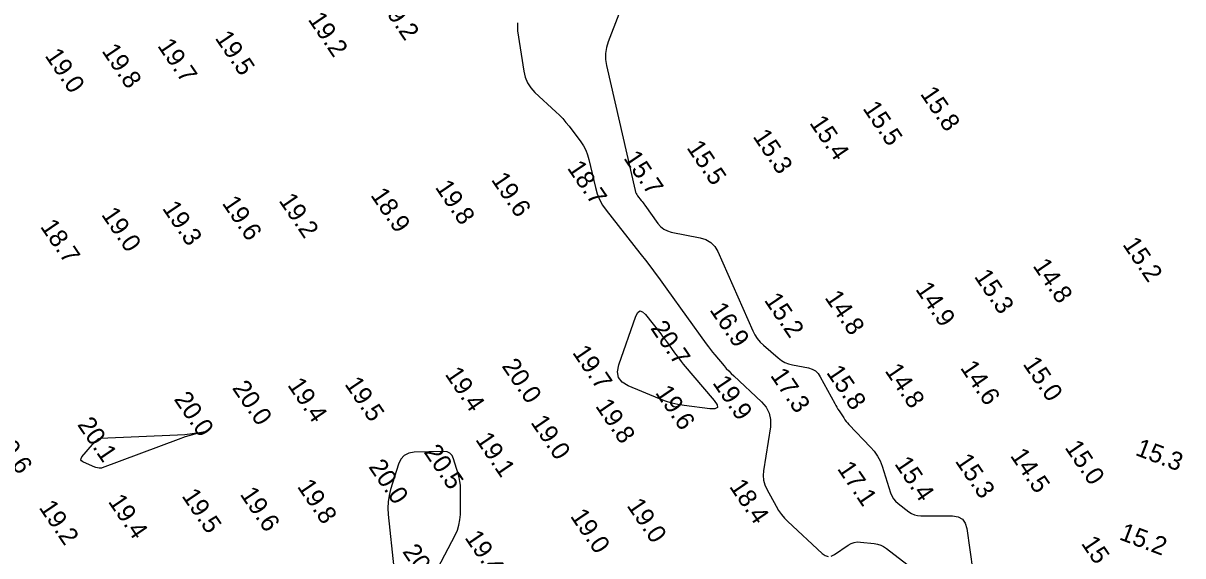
# Model space of a CAD drawing. Extents: x 824616 to 827440, y 158441 to 163197.
# Drawn here: x 826605.2 to 826924.3, y 160082.7 to 160229.3 of the extents above; entities that cross this region are included whole.
import ezdxf

# ---------------------------------------------------------------- set-up
doc = ezdxf.new("R2010")
doc.units = 0
for name, color, linetype in [('V-CHAN-CONT-EL16', 7, 'Continuous'), ('V-CHAN-CONT-EL18', 7, 'Continuous'), ('V-CHAN-CONT-EL20', 7, 'Continuous'), ('V-TOPO-SOUN', 7, 'Continuous')]:
    doc.layers.add(name, color=color, linetype=linetype)

msp = doc.modelspace()

# ---------------------------------------------------------------- linework, layer by layer
at = {"layer": 'V-CHAN-CONT-EL16'}
msp.add_lwpolyline([(826769.1, 160231.82), (826766.18, 160224.2), (826765.7, 160222.6), (826765.46, 160220.98), (826765.47, 160219.34), (826765.72, 160217.69), (826773.6, 160183.22), (826773.71, 160182.84), (826773.86, 160182.48), (826774.05, 160182.13), (826774.28, 160181.8), (826775.28, 160180.53), (826775.52, 160180.22), (826775.77, 160179.9), (826776.01, 160179.57), (826776.24, 160179.25), (826779.88, 160174.17), (826780.62, 160173.31), (826781.48, 160172.63), (826782.46, 160172.13), (826783.55, 160171.82), (826791.51, 160170.28), (826793.09, 160169.79), (826794.43, 160168.98), (826795.51, 160167.86), (826796.34, 160166.43), (826805.94, 160144.67), (826806.51, 160143.54), (826807.19, 160142.51), (826807.99, 160141.55), (826808.9, 160140.68), (826812.98, 160137.16), (826813.86, 160136.49), (826814.81, 160135.96), (826815.82, 160135.55), (826816.89, 160135.27), (826821.29, 160134.43), (826822.32, 160134.12), (826823.21, 160133.61), (826823.95, 160132.92), (826824.55, 160132.02), (826828.52, 160124.6), (826828.8, 160124.09), (826829.09, 160123.59), (826829.39, 160123.09), (826829.71, 160122.6), (826830.99, 160120.66), (826831.32, 160120.18), (826831.68, 160119.72), (826832.05, 160119.28), (826832.44, 160118.85), (826838.37, 160112.66), (826839.39, 160111.47), (826840.26, 160110.18), (826840.98, 160108.81), (826841.54, 160107.34), (826843.88, 160100.03), (826844.22, 160099.18), (826844.68, 160098.41), (826845.25, 160097.73), (826845.93, 160097.12), (826848.89, 160094.85), (826849.66, 160094.35), (826850.47, 160094), (826851.33, 160093.79), (826852.24, 160093.71), (826860.9, 160093.7), (826862.46, 160093.48), (826863.64, 160092.82), (826864.45, 160091.74), (826864.88, 160090.22), (826867.3, 160072.58)], dxfattribs=at)
at = {"layer": 'V-CHAN-CONT-EL18'}
for points in [[(826741.21, 160229.44), (826741.25, 160227.19), (826742.94, 160216.11), (826743.33, 160214.44), (826743.98, 160212.91), (826744.88, 160211.52), (826746.04, 160210.26), (826751.79, 160204.96), (826752.76, 160204.02), (826753.68, 160203.04), (826754.56, 160202.02), (826755.4, 160200.96), (826758.65, 160196.63), (826759.4, 160195.52), (826760.02, 160194.35), (826760.51, 160193.12), (826760.88, 160191.83), (826762.65, 160184.08), (826763.13, 160182.39), (826763.79, 160180.78), (826764.62, 160179.26), (826765.63, 160177.83), (826774.91, 160166.03), (826776.81, 160163.59), (826778.68, 160161.13), (826780.53, 160158.65), (826782.34, 160156.15), (826793.17, 160141.04), (826793.74, 160140.26), (826794.32, 160139.5), (826794.93, 160138.74), (826795.54, 160137.99), (826798.05, 160135.04), (826798.68, 160134.31), (826799.34, 160133.6), (826800.02, 160132.92), (826800.72, 160132.25), (826808.4, 160125.13), (826809.68, 160123.65), (826810.51, 160122), (826810.89, 160120.2), (826810.8, 160118.24), (826808.93, 160106.08), (826808.84, 160104.77), (826808.95, 160103.5), (826809.27, 160102.26), (826809.81, 160101.06), (826812.38, 160096.34), (826813.07, 160095.19), (826813.84, 160094.11), (826814.69, 160093.09), (826815.63, 160092.14), (826825.09, 160083.33), (826825.89, 160082.76), (826826.72, 160082.53)], [(826827.57, 160082.63), (826828.44, 160083.07), (826832.22, 160085.66), (826833.02, 160086.11), (826833.85, 160086.4), (826834.73, 160086.53), (826835.64, 160086.51), (826839.38, 160086.08), (826840.29, 160085.92), (826841.16, 160085.64), (826841.97, 160085.24), (826842.74, 160084.73), (826850.76, 160078.59)]]:
    msp.add_lwpolyline(points, dxfattribs=at)
at = {"layer": 'V-CHAN-CONT-EL20'}
for points in [[(826781.69, 160142.43), (826782.2, 160141.74), (826782.71, 160141.04), (826784.73, 160138.23), (826785.24, 160137.53), (826785.76, 160136.84), (826786.3, 160136.16), (826786.85, 160135.5), (826795.38, 160125.43), (826796.17, 160124.27), (826796.22, 160123.51), (826795.56, 160123.15), (826794.16, 160123.18), (826787.13, 160124.08), (826785.39, 160124.37), (826783.67, 160124.77), (826781.99, 160125.28), (826780.34, 160125.9), (826771.68, 160129.52), (826770.02, 160130.51), (826769.05, 160131.79), (826768.74, 160133.37), (826769.12, 160135.26), (826773.79, 160148.66), (826774.3, 160149.68), (826774.92, 160150.1), (826775.64, 160149.91), (826776.46, 160149.1), (826780.63, 160143.8), (826781.16, 160143.12)], [(826624.73, 160107.17), (826624.51, 160107.25), (826624.3, 160107.35), (826621.67, 160108.6), (826621.27, 160108.86), (826621.09, 160109.17), (826621.13, 160109.53), (826621.39, 160109.94), (826624.32, 160113.36), (826624.47, 160113.54), (826624.63, 160113.71), (826624.79, 160113.88), (826624.96, 160114.05), (826625.63, 160114.72), (826625.8, 160114.87), (826625.99, 160114.98), (826626.2, 160115.04), (826626.43, 160115.07), (826647.64, 160116.01), (826649.68, 160116.14), (826651.7, 160116.34), (826653.72, 160116.61), (826655.73, 160116.96), (826653.74, 160116.53), (826651.77, 160116.02), (826649.82, 160115.43), (826647.9, 160114.76), (826626.98, 160106.92), (826626.76, 160106.86), (826626.54, 160106.83), (826626.31, 160106.82), (826626.09, 160106.86), (826625.18, 160107.05), (826624.95, 160107.11)]]:
    msp.add_lwpolyline(points, close=True, dxfattribs=at)
msp.add_lwpolyline([(826719.29, 160079.3), (826724.07, 160088.39), (826724.69, 160089.76), (826725.13, 160091.16), (826725.4, 160092.61), (826725.5, 160094.11), (826725.54, 160101.03), (826725.5, 160102.11), (826725.39, 160103.18), (826725.19, 160104.23), (826724.91, 160105.28), (826723.64, 160109.44), (826723.23, 160110.35), (826722.62, 160110.99), (826721.83, 160111.36), (826720.83, 160111.46), (826712.84, 160111.23), (826711.3, 160110.99), (826710.05, 160110.35), (826709.11, 160109.32), (826708.46, 160107.9), (826706.32, 160100.97), (826705.89, 160099.27), (826705.63, 160097.55), (826705.55, 160095.81), (826705.64, 160094.05), (826707.16, 160079.43)], dxfattribs=at)

# ---------------------------------------------------------------- texts
at = {"layer": 'V-TOPO-SOUN'}
for s, rotation, p in [('19.2 ', 304.2, (826703.06, 160234.93)), ('19.2 ', 304.2, (826683.43, 160230.34)), ('19.5 ', 304.2, (826657.84, 160225.22)), ('19.7 ', 304.2, (826642, 160223.1)), ('19.0 ', 304.2, (826611.02, 160220.37)), ('19.8 ', 304.2, (826626.69, 160221.66)), ('15.8 ', 304.2, (826851.9, 160209.86)), ('15.5 ', 304.2, (826836.07, 160205.85)), ('15.4 ', 304.2, (826821.41, 160201.86)), ('15.3 ', 304.2, (826805.83, 160198.12)), ('15.5 ', 304.2, (826787.62, 160195.03)), ('15.7 ', 304.2, (826770.26, 160192.19)), ('18.7 ', 304.2, (826754.75, 160189.46)), ('19.8 ', 304.2, (826718.41, 160184.14)), ('19.6 ', 304.2, (826733.83, 160186.25)), ('19.2 ', 304.2, (826675.4, 160180.48)), ('18.9 ', 304.2, (826700.65, 160181.96)), ('19.3 ', 304.2, (826643.33, 160178.37)), ('19.6 ', 304.2, (826659.78, 160179.76)), ('19.0 ', 304.2, (826626.57, 160176.63)), ('18.7 ', 304.2, (826609.75, 160173.34)), ('15.2 ', 304.2, (826907.57, 160168.4)), ('14.8 ', 304.2, (826882.86, 160162.53)), ('15.3 ', 304.2, (826866.73, 160159.59)), ('14.9 ', 304.2, (826850.59, 160156.08)), ('15.2 ', 304.2, (826808.95, 160153.07)), ('14.8 ', 304.2, (826825.62, 160153.76)), ('16.9 ', 304.2, (826793.94, 160150.41)), ('20.7 ', 304.2, (826777.67, 160145.37)), ('19.7 ', 304.2, (826756.18, 160138.65)), ('19.4 ', 304.2, (826721.12, 160132.68)), ('20.0 ', 304.2, (826736.75, 160134.95)), ('15.8 ', 304.2, (826826.06, 160133.16)), ('14.8 ', 304.2, (826842.16, 160133.63)), ('14.6 ', 304.2, (826862.9, 160134.45)), ('15.0 ', 304.2, (826880.13, 160135.5)), ('19.4 ', 304.2, (826677.79, 160129.7)), ('19.5 ', 304.2, (826693.51, 160129.96)), ('19.9 ', 304.2, (826794.75, 160130.32)), ('17.3 ', 304.2, (826810.64, 160132.35)), ('20.0 ', 304.2, (826662.57, 160128.9)), ('19.6 ', 304.2, (826778.98, 160127.62)), ('20.0 ', 304.2, (826646.54, 160125.83)), ('19.8 ', 304.2, (826762.51, 160123.92)), ('20.1 ', 304.2, (826619.97, 160118.82)), ('19.0 ', 304.2, (826744.7, 160119.43)), ('19.6 ', 304.2, (826596.63, 160115.54)), ('19.1 ', 304.2, (826729.5, 160114.7)), ('20.5 ', 304.2, (826715.3, 160111.27)), ('14.5 ', 304.2, (826876.65, 160110.27)), ('15.0 ', 304.2, (826891.66, 160112.51)), ('15.3 ', 339.2, (826910.97, 160110.53)), ('20.0 ', 304.2, (826700.1, 160107.22)), ('15.4 ', 304.2, (826844.81, 160108.02)), ('15.3 ', 304.2, (826861.49, 160108.79)), ('17.1 ', 304.2, (826829.06, 160106.69)), ('19.8 ', 304.2, (826680.45, 160101.78)), ('18.4 ', 304.2, (826799.34, 160101.79)), ('19.4 ', 304.2, (826628.43, 160097.64)), ('19.5 ', 304.2, (826648.69, 160099.19)), ('19.6 ', 304.2, (826664.72, 160099.64)), ('19.2 ', 304.2, (826609.4, 160095.99)), ('19.0 ', 304.2, (826771.15, 160096.53)), ('19.0 ', 304.2, (826755.58, 160093.64)), ('15.2 ', 339.2, (826906.54, 160087.3)), ('19.4 ', 304.2, (826726.55, 160087.7)), ('15.2 ', 304.2, (826896.17, 160086.14)), ('20.1 ', 304.2, (826709.42, 160083.86))]:
    msp.add_text(s, height=5, rotation=rotation, dxfattribs=at).set_placement(p)

doc.saveas('drawing.dxf')
